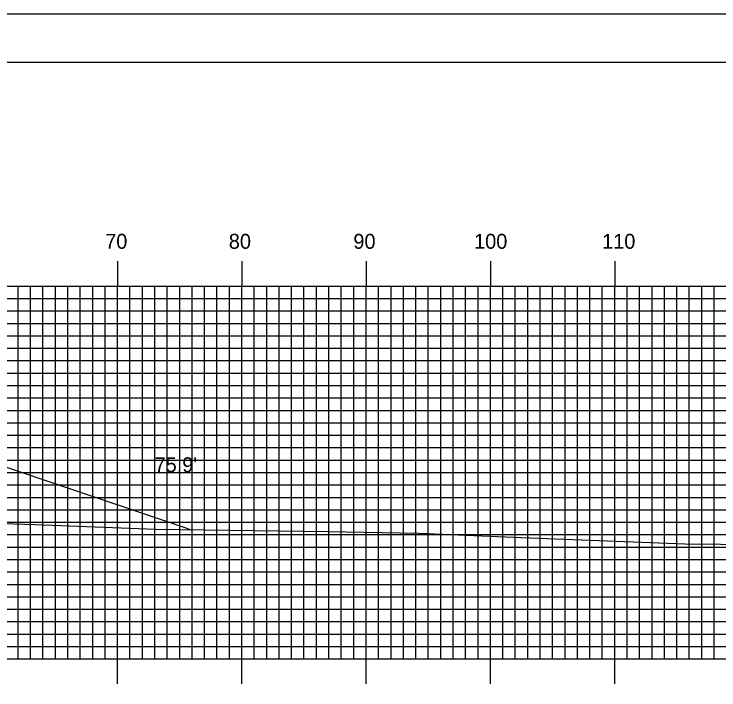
# Model space of a CAD drawing. Extents: x 1807832 to 1808175, y 442591 to 442811.
# Drawn here: x 1808059.5 to 1808116.2, y 442756.2 to 442810.5 of the extents above; entities that cross this region are included whole.
import ezdxf

# ---------------------------------------------------------------- set-up
doc = ezdxf.new("R2010")
doc.units = 0
for name, color, linetype in [('BORDER', 7, 'Continuous'), ('D_Roadway_SlopeLines', 7, 'Continuous'), ('D_Text_Standard', 7, 'Continuous'), ('H_V ANNOTATION', 7, 'Continuous'), ('MAJOR', 7, 'Continuous'), ('MINOR', 7, 'Continuous'), ('PLOT BOUNDARY', 7, 'Continuous'), ('S_Roadway_Centerline', 7, 'Continuous')]:
    doc.layers.add(name, color=color, linetype=linetype)

msp = doc.modelspace()

# ---------------------------------------------------------------- linework, layer by layer
at = {"layer": 'BORDER'}
msp.add_lwpolyline([(1807848.185, 442596.665), (1808168.185, 442596.665), (1808168.185, 442806.665), (1807848.185, 442806.665)], close=True, dxfattribs=at)
at = {"layer": 'D_Roadway_SlopeLines'}
msp.add_line((1808073.28, 442769.2), (1808073.68, 442769.064), dxfattribs=at)
msp.add_lwpolyline([(1808051.295, 442776.644), (1808054.526, 442775.55), (1808073.28, 442769.2)], dxfattribs=at)
at = {"layer": 'MAJOR'}
for p, q in [((1808067.785, 442790.669), (1808067.785, 442788.665)), ((1808077.785, 442790.669), (1808077.785, 442788.665)), ((1808087.785, 442790.669), (1808087.785, 442788.665)), ((1808097.785, 442790.669), (1808097.785, 442788.665)), ((1808107.785, 442790.669), (1808107.785, 442788.665)), ((1807857.785, 442788.665), (1808137.785, 442788.665)), ((1807857.785, 442788.665), (1808137.785, 442788.665)), ((1808067.785, 442758.665), (1808067.785, 442788.665)), ((1808077.785, 442758.665), (1808077.785, 442788.665)), ((1808087.785, 442758.665), (1808087.785, 442788.665)), ((1808097.785, 442758.665), (1808097.785, 442788.665)), ((1808107.785, 442758.665), (1808107.785, 442788.665)), ((1807857.785, 442783.665), (1808137.785, 442783.665)), ((1807857.785, 442778.665), (1808137.785, 442778.665)), ((1807857.785, 442773.665), (1808137.785, 442773.665)), ((1807857.785, 442768.665), (1808137.785, 442768.665)), ((1807857.785, 442763.665), (1808137.785, 442763.665)), ((1807857.785, 442758.665), (1808137.785, 442758.665)), ((1807857.785, 442758.665), (1808137.785, 442758.665)), ((1808067.785, 442756.661), (1808067.785, 442758.665)), ((1808077.785, 442756.661), (1808077.785, 442758.665)), ((1808087.785, 442756.661), (1808087.785, 442758.665)), ((1808097.785, 442756.661), (1808097.785, 442758.665)), ((1808107.785, 442756.661), (1808107.785, 442758.665))]:
    msp.add_line(p, q, dxfattribs=at)
at = {"layer": 'MINOR'}
for p, q in [((1808059.785, 442758.665), (1808059.785, 442788.665)), ((1808060.785, 442758.665), (1808060.785, 442788.665)), ((1808061.785, 442758.665), (1808061.785, 442788.665)), ((1808062.785, 442758.665), (1808062.785, 442788.665)), ((1808063.785, 442758.665), (1808063.785, 442788.665)), ((1808064.785, 442758.665), (1808064.785, 442788.665)), ((1808065.785, 442758.665), (1808065.785, 442788.665)), ((1808066.785, 442758.665), (1808066.785, 442788.665)), ((1808068.785, 442758.665), (1808068.785, 442788.665)), ((1808069.785, 442758.665), (1808069.785, 442788.665)), ((1808070.785, 442758.665), (1808070.785, 442788.665)), ((1808071.785, 442758.665), (1808071.785, 442788.665)), ((1808072.785, 442758.665), (1808072.785, 442788.665)), ((1808073.785, 442758.665), (1808073.785, 442788.665)), ((1808074.785, 442758.665), (1808074.785, 442788.665)), ((1808075.785, 442758.665), (1808075.785, 442788.665)), ((1808076.785, 442758.665), (1808076.785, 442788.665)), ((1808078.785, 442758.665), (1808078.785, 442788.665)), ((1808079.785, 442758.665), (1808079.785, 442788.665)), ((1808080.785, 442758.665), (1808080.785, 442788.665)), ((1808081.785, 442758.665), (1808081.785, 442788.665)), ((1808082.785, 442758.665), (1808082.785, 442788.665)), ((1808083.785, 442758.665), (1808083.785, 442788.665)), ((1808084.785, 442758.665), (1808084.785, 442788.665)), ((1808085.785, 442758.665), (1808085.785, 442788.665)), ((1808086.785, 442758.665), (1808086.785, 442788.665)), ((1808088.785, 442758.665), (1808088.785, 442788.665)), ((1808089.785, 442758.665), (1808089.785, 442788.665)), ((1808090.785, 442758.665), (1808090.785, 442788.665)), ((1808091.785, 442758.665), (1808091.785, 442788.665)), ((1808092.785, 442758.665), (1808092.785, 442788.665)), ((1808093.785, 442758.665), (1808093.785, 442788.665)), ((1808094.785, 442758.665), (1808094.785, 442788.665)), ((1808095.785, 442758.665), (1808095.785, 442788.665)), ((1808096.785, 442758.665), (1808096.785, 442788.665)), ((1808098.785, 442758.665), (1808098.785, 442788.665)), ((1808099.785, 442758.665), (1808099.785, 442788.665)), ((1808100.785, 442758.665), (1808100.785, 442788.665)), ((1808101.785, 442758.665), (1808101.785, 442788.665)), ((1808102.785, 442758.665), (1808102.785, 442788.665)), ((1808103.785, 442758.665), (1808103.785, 442788.665)), ((1808104.785, 442758.665), (1808104.785, 442788.665)), ((1808105.785, 442758.665), (1808105.785, 442788.665)), ((1808106.785, 442758.665), (1808106.785, 442788.665)), ((1808108.785, 442758.665), (1808108.785, 442788.665)), ((1808109.785, 442758.665), (1808109.785, 442788.665)), ((1808110.785, 442758.665), (1808110.785, 442788.665)), ((1808111.785, 442758.665), (1808111.785, 442788.665)), ((1808112.785, 442758.665), (1808112.785, 442788.665)), ((1808113.785, 442758.665), (1808113.785, 442788.665)), ((1808114.785, 442758.665), (1808114.785, 442788.665)), ((1808115.785, 442758.665), (1808115.785, 442788.665)), ((1807857.785, 442787.665), (1808137.785, 442787.665)), ((1807857.785, 442786.665), (1808137.785, 442786.665)), ((1807857.785, 442785.665), (1808137.785, 442785.665)), ((1807857.785, 442784.665), (1808137.785, 442784.665)), ((1807857.785, 442782.665), (1808137.785, 442782.665)), ((1807857.785, 442781.665), (1808137.785, 442781.665)), ((1807857.785, 442780.665), (1808137.785, 442780.665)), ((1807857.785, 442779.665), (1808137.785, 442779.665)), ((1807857.785, 442777.665), (1808137.785, 442777.665)), ((1807857.785, 442776.665), (1808137.785, 442776.665)), ((1807857.785, 442775.665), (1808137.785, 442775.665)), ((1807857.785, 442774.665), (1808137.785, 442774.665)), ((1807857.785, 442772.665), (1808137.785, 442772.665)), ((1807857.785, 442771.665), (1808137.785, 442771.665)), ((1807857.785, 442770.665), (1808137.785, 442770.665)), ((1807857.785, 442769.665), (1808137.785, 442769.665)), ((1807857.785, 442767.665), (1808137.785, 442767.665)), ((1807857.785, 442766.665), (1808137.785, 442766.665)), ((1807857.785, 442765.665), (1808137.785, 442765.665)), ((1807857.785, 442764.665), (1808137.785, 442764.665)), ((1807857.785, 442762.665), (1808137.785, 442762.665)), ((1807857.785, 442761.665), (1808137.785, 442761.665)), ((1807857.785, 442760.665), (1808137.785, 442760.665)), ((1807857.785, 442759.665), (1808137.785, 442759.665))]:
    msp.add_line(p, q, dxfattribs=at)
at = {"layer": 'PLOT BOUNDARY'}
msp.add_lwpolyline([(1807831.998, 442590.547), (1808171.998, 442590.547), (1808171.998, 442810.547), (1807831.998, 442810.547)], close=True, dxfattribs=at)
at = {"layer": 'S_Roadway_Centerline'}
msp.add_lwpolyline([(1808050.253, 442769.825), (1808061.117, 442769.478), (1808070.845, 442769.099), (1808084.68, 442768.929), (1808092.017, 442768.785), (1808100.264, 442768.446), (1808113.427, 442767.92), (1808127.801, 442767.78), (1808130.816, 442767.75), (1808133.275, 442767.438), (1808137.785, 442766.961)], dxfattribs=at)

# ---------------------------------------------------------------- texts
at = {"layer": 'D_Text_Standard'}
msp.add_text("75.9'", height=1.2, dxfattribs=at).set_placement((1808070.76, 442773.688))
at = {"layer": 'H_V ANNOTATION'}
for s, p in [('70', (1808066.789, 442791.665)), ('80', (1808076.736, 442791.665)), ('90', (1808086.757, 442791.665)), ('100', (1808096.468, 442791.665)), ('110', (1808106.768, 442791.665))]:
    msp.add_text(s, height=1.2, dxfattribs=at).set_placement(p)

doc.saveas('drawing.dxf')
